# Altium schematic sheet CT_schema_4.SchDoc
size 294 x 169 mm
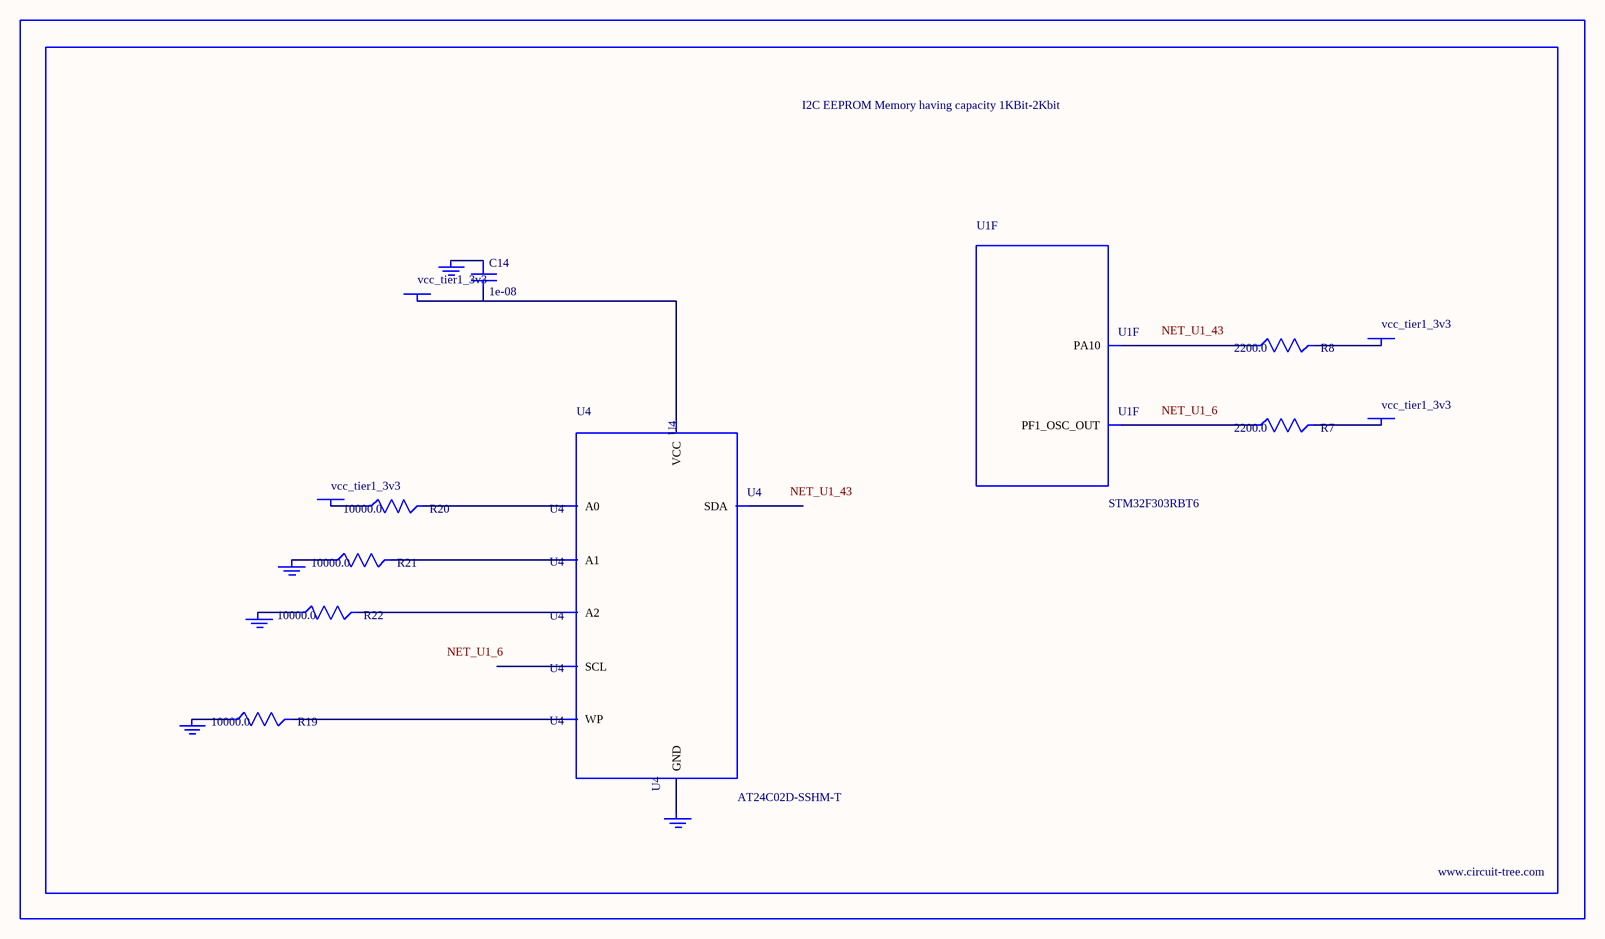
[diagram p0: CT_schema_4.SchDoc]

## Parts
BORDER3  (no value)
C14  1e-08  [C0402]
GND_INSTANCE_3_0  (no value)
GND_INSTANCE_3_1  (no value)
GND_INSTANCE_3_2  (no value)
GND_INSTANCE_3_3  (no value)
GND_INSTANCE_3_4  (no value)
POWER_INSTANCE_3_0  vcc_tier1_3v3
POWER_INSTANCE_3_1  vcc_tier1_3v3
POWER_INSTANCE_3_2  vcc_tier1_3v3
POWER_INSTANCE_3_3  vcc_tier1_3v3
R7  2200.0  [R0603]
R8  2200.0  [R0603]
R19  10000.0  [R0603]
R20  10000.0  [R0603]
R21  10000.0  [R0603]
R22  10000.0  [R0603]
U1  STM32F303RBT6  [LQFP64]  (part F of 7)
U4  AT24C02D-SSHM-T  [AT24C02D]

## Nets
NetC14_1: C14.1 GND_INSTANCE_3_3.0(GND)
NetC14_2: C14.2 POWER_INSTANCE_3_1.0(PWR) U4.8(VCC)
NetGND_INSTANCE_3_0_0: GND_INSTANCE_3_0.0(GND) R21.1
NetGND_INSTANCE_3_1_0: GND_INSTANCE_3_1.0(GND) R22.1
NetGND_INSTANCE_3_2_0: GND_INSTANCE_3_2.0(GND) R19.1
NetGND_INSTANCE_3_4_0: GND_INSTANCE_3_4.0(GND) U4.4(GND)
NetPOWER_INSTANCE_3_0_0: POWER_INSTANCE_3_0.0(PWR) R20.1
NetPOWER_INSTANCE_3_2_0: POWER_INSTANCE_3_2.0(PWR) R7.2
NetPOWER_INSTANCE_3_3_0: POWER_INSTANCE_3_3.0(PWR) R8.2
NetR7_1: R7.1 U1.6(PF1_OSC_OUT)
NetR8_1: R8.1 U1.43(PA10)
NetR19_2: R19.2 U4.7(WP)
NetR20_2: R20.2 U4.1(A0)
NetR21_2: R21.2 U4.2(A1)
NetR22_2: R22.2 U4.3(A2)

Not connected (* = marked no-connect by the designer): U4 5(SDA) 6(SCL)

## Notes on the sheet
- Labels drawn without touching a wire or pin: NET_U1_6, NET_U1_43

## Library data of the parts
BORDER3 = BORDER_PAGE3
C14 = C0402C103K3RAC
GND_INSTANCE_3_0-GND_INSTANCE_3_4 = GND
POWER_INSTANCE_3_0-POWER_INSTANCE_3_3 = PWR
R7 R8 = RC0603JR-072K2L
R19-R22 = RC0603JR-0710KL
